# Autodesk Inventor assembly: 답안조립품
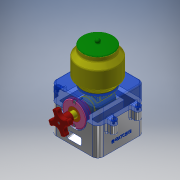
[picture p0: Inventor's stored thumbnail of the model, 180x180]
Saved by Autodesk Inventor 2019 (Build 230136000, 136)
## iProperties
Created: 2022-03
Part Number: 답안조립품
Material: 일반
Document SubType Name: Assembly
Designer: LINE501-1
Author: LINE501-1
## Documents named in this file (11)
- C:\Users\LINE501-1\Desktop\720306V1007\답안조립품.iam
- C:\Users\LINE501-1\Desktop\720306V1007\본체.ipt
- C:\Users\LINE501-1\Desktop\720306V1007\본체커버.ipt
- C:\Users\LINE501-1\Desktop\720306V1007\핸들축.ipt
- C:\Users\LINE501-1\Desktop\720306V1007\베어링 부시.ipt
- C:\Users\LINE501-1\Desktop\720306V1007\앞커버.ipt
- C:\Users\LINE501-1\Desktop\720306V1007\핸들.ipt
- C:\Users\LINE501-1\Desktop\720306V1007\볼트 M3x12.ipt
- C:\Users\LINE501-1\Desktop\720306V1007\용기.ipt
- C:\Users\LINE501-1\Desktop\720306V1007\볼트 M4x12.ipt
- C:\Users\LINE501-1\Desktop\720306V1007\용기캡.ipt
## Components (2 placed, 2 different names)
1. 핸들축:1 — 각도:1
2. 핸들:1
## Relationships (1: Angle 1)
- 각도:1 [Angle]: 핸들축:1
